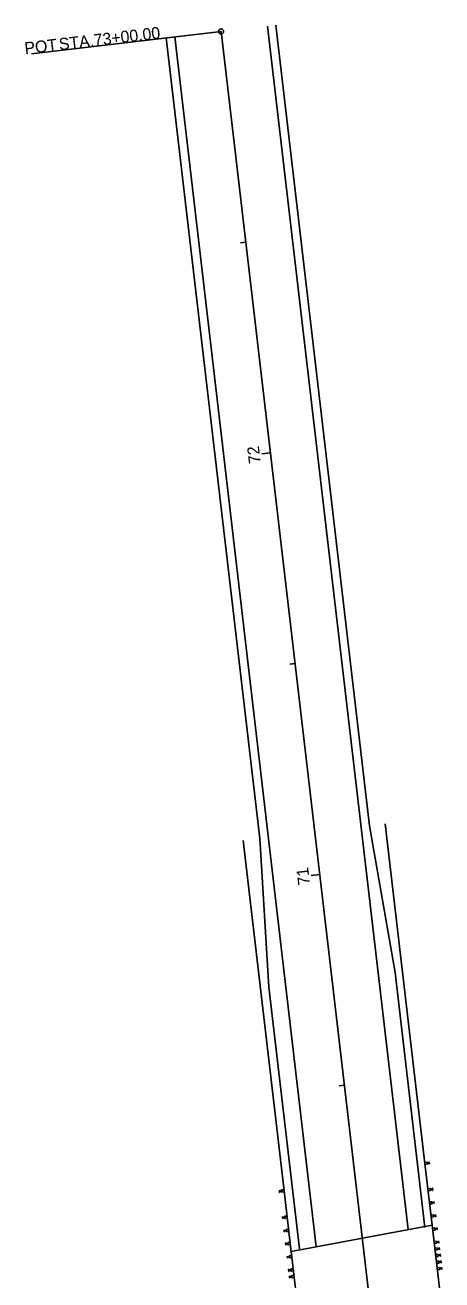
# Model space of a CAD drawing. Extents: x 27625 to 127752, y 6088 to 302357.
# Drawn here: x 127645.5 to 127743.8, y 302061.4 to 302357.1 of the extents above; entities that cross this region are included whole.
import ezdxf

# ---------------------------------------------------------------- set-up
doc = ezdxf.new("R2010")
doc.units = 0
for name, color, linetype in [('DR_X_Cells', 7, 'Continuous'), ('RW_X_CL_100_Bearings', 7, 'Continuous'), ('RW_X_CL_100_Cardinal_Points', 7, 'Continuous'), ('RW_X_CL_100_Curve_Data', 7, 'Continuous'), ('RW_X_CL_100_Distances', 7, 'Continuous'), ('RW_X_CL_100_Stations', 7, 'Continuous'), ('SC_Scratch13', 7, 'Continuous'), ('SC_Scratch2', 7, 'Continuous'), ('SV_P_Control_Cells_Set', 7, 'Continuous'), ('SV_X_Mon_Cells_Found', 7, 'Continuous'), ('SV_X_Random_Point', 7, 'Continuous'), ('UT_X_Telecom_Cells', 7, 'Continuous')]:
    doc.layers.add(name, color=color, linetype=linetype)

msp = doc.modelspace()

# ---------------------------------------------------------------- linework, layer by layer
at = {"layer": 'DR_X_Cells'}
for p, q in [((127697.52, 302305.96), (127696.33, 302305.82)), ((127703.33, 302256.3), (127701.34, 302256.07)), ((127709.14, 302206.64), (127707.94, 302206.5)), ((127714.94, 302156.98), (127712.96, 302156.75)), ((127720.75, 302107.32), (127719.56, 302107.18))]:
    msp.add_line(p, q, dxfattribs=at)
at = {"layer": 'RW_X_CL_100_Bearings'}
for p, q in [((127708.23, 302068.08), (127741.47, 302074.34)), ((127743.22, 302059.45), (127741.47, 302074.34)), ((127709.97, 302053.18), (127708.23, 302068.08))]:
    msp.add_line(p, q, dxfattribs=at)
at = {"layer": 'RW_X_CL_100_Cardinal_Points'}
for p, q in [((127741.47, 302074.34), (127739.78, 302088.84)), ((127739.78, 302088.84), (127739.78, 302088.84)), ((127708.25, 302067.92), (127706.55, 302082.42)), ((127706.55, 302082.42), (127706.55, 302082.42))]:
    msp.add_line(p, q, dxfattribs=at)
at = {"layer": 'RW_X_CL_100_Curve_Data'}
for p, q in [((127739.75, 302089.09), (127740.28, 302089.16)), ((127740.34, 302088.65), (127739.81, 302088.59)), ((127740.34, 302088.65), (127740.28, 302089.16)), ((127740.31, 302089.16), (127740.28, 302089.16)), ((127740.34, 302088.95), (127740.31, 302089.16)), ((127740.37, 302088.65), (127740.34, 302088.65)), ((127740.37, 302088.65), (127740.35, 302088.86)), ((127740.76, 302088.97), (127740.37, 302088.93)), ((127740.77, 302088.94), (127740.38, 302088.9)), ((127740.8, 302089.22), (127740.77, 302089.21)), ((127740.79, 302089.01), (127740.77, 302089.21)), ((127740.86, 302088.71), (127740.8, 302089.22)), ((127740.83, 302088.71), (127740.8, 302088.91)), ((127740.86, 302088.71), (127740.83, 302088.71)), ((127705.52, 302082.04), (127705.47, 302082.55)), ((127705.47, 302082.55), (127705.5, 302082.55)), ((127705.53, 302082.34), (127705.5, 302082.55)), ((127705.52, 302082.04), (127705.56, 302082.04)), ((127705.56, 302082.04), (127705.54, 302082.25)), ((127705.56, 302082.32), (127705.95, 302082.36)), ((127705.56, 302082.29), (127705.96, 302082.33)), ((127705.96, 302082.6), (127705.99, 302082.61)), ((127705.98, 302082.4), (127705.96, 302082.6)), ((127706.52, 302082.67), (127705.99, 302082.61)), ((127706.05, 302082.1), (127705.99, 302082.61)), ((127706.02, 302082.1), (127705.99, 302082.3)), ((127706.02, 302082.1), (127706.05, 302082.1)), ((127706.05, 302082.1), (127706.58, 302082.16)), ((127740.47, 302082.89), (127741, 302082.95)), ((127741.06, 302082.44), (127740.53, 302082.38)), ((127741.06, 302082.44), (127741, 302082.95)), ((127741.04, 302082.95), (127741, 302082.95)), ((127741.06, 302082.75), (127741.04, 302082.95)), ((127741.1, 302082.45), (127741.06, 302082.44)), ((127741.1, 302082.45), (127741.07, 302082.65)), ((127741.49, 302082.76), (127741.1, 302082.72)), ((127741.49, 302082.73), (127741.1, 302082.69)), ((127741.53, 302083.01), (127741.49, 302083.01)), ((127741.52, 302082.8), (127741.49, 302083.01)), ((127741.59, 302082.5), (127741.53, 302083.01)), ((127741.55, 302082.5), (127741.53, 302082.71)), ((127741.59, 302082.5), (127741.55, 302082.5)), ((127740.84, 302079.78), (127741.37, 302079.84)), ((127741.42, 302079.34), (127740.9, 302079.28)), ((127741.4, 302079.85), (127741.37, 302079.84)), ((127741.42, 302079.34), (127741.37, 302079.84)), ((127741.43, 302079.64), (127741.4, 302079.85)), ((127741.46, 302079.34), (127741.42, 302079.34)), ((127741.46, 302079.34), (127741.44, 302079.55)), ((127741.85, 302079.66), (127741.46, 302079.61)), ((127741.86, 302079.63), (127741.46, 302079.58)), ((127741.89, 302079.91), (127741.86, 302079.9)), ((127741.88, 302079.7), (127741.86, 302079.9)), ((127741.95, 302079.4), (127741.89, 302079.91)), ((127741.92, 302079.4), (127741.89, 302079.6)), ((127741.95, 302079.4), (127741.92, 302079.4)), ((127706.25, 302075.83), (127706.19, 302076.34)), ((127706.19, 302076.34), (127706.23, 302076.34)), ((127706.25, 302076.14), (127706.23, 302076.34)), ((127706.25, 302075.83), (127706.29, 302075.84)), ((127706.29, 302075.84), (127706.26, 302076.04)), ((127706.29, 302076.11), (127706.68, 302076.16)), ((127706.29, 302076.08), (127706.68, 302076.12)), ((127706.68, 302076.4), (127706.72, 302076.4)), ((127706.71, 302076.19), (127706.68, 302076.4)), ((127707.25, 302076.46), (127706.72, 302076.4)), ((127706.78, 302075.89), (127706.72, 302076.4)), ((127706.74, 302075.89), (127706.72, 302076.1)), ((127706.74, 302075.89), (127706.78, 302075.89)), ((127706.78, 302075.89), (127707.31, 302075.96)), ((127741.2, 302076.68), (127741.73, 302076.74)), ((127741.79, 302076.23), (127741.26, 302076.17)), ((127741.76, 302076.75), (127741.73, 302076.74)), ((127741.79, 302076.23), (127741.73, 302076.74)), ((127741.79, 302076.54), (127741.76, 302076.75)), ((127741.82, 302076.24), (127741.79, 302076.23)), ((127741.82, 302076.24), (127741.8, 302076.45)), ((127742.22, 302076.56), (127741.82, 302076.51)), ((127742.22, 302076.53), (127741.83, 302076.48)), ((127742.26, 302076.8), (127742.22, 302076.8)), ((127742.24, 302076.59), (127742.22, 302076.8)), ((127742.32, 302076.3), (127742.26, 302076.8)), ((127742.28, 302076.29), (127742.26, 302076.5)), ((127742.32, 302076.3), (127742.28, 302076.29)), ((127706.61, 302072.73), (127706.55, 302073.24)), ((127706.55, 302073.24), (127706.59, 302073.24)), ((127706.61, 302073.03), (127706.59, 302073.24)), ((127706.61, 302072.73), (127706.65, 302072.73)), ((127706.65, 302072.73), (127706.63, 302072.94)), ((127706.65, 302073.01), (127707.04, 302073.05)), ((127706.65, 302072.97), (127707.05, 302073.02)), ((127707.05, 302073.29), (127707.08, 302073.3)), ((127707.07, 302073.09), (127707.05, 302073.29)), ((127707.61, 302073.36), (127707.08, 302073.3)), ((127707.14, 302072.79), (127707.08, 302073.3)), ((127707.1, 302072.79), (127707.08, 302072.99)), ((127707.1, 302072.79), (127707.14, 302072.79)), ((127707.14, 302072.79), (127707.67, 302072.85)), ((127741.56, 302073.58), (127742.09, 302073.64)), ((127742.15, 302073.13), (127741.62, 302073.07)), ((127742.15, 302073.13), (127742.09, 302073.64)), ((127742.13, 302073.64), (127742.09, 302073.64)), ((127742.15, 302073.43), (127742.13, 302073.64)), ((127742.19, 302073.13), (127742.15, 302073.13)), ((127742.19, 302073.13), (127742.16, 302073.34)), ((127742.58, 302073.45), (127742.19, 302073.41)), ((127742.58, 302073.42), (127742.19, 302073.38)), ((127742.62, 302073.7), (127742.58, 302073.69)), ((127742.61, 302073.49), (127742.58, 302073.69)), ((127742.68, 302073.19), (127742.62, 302073.7)), ((127742.64, 302073.19), (127742.62, 302073.39)), ((127742.68, 302073.19), (127742.64, 302073.19)), ((127706.92, 302070.13), (127706.95, 302070.14)), ((127706.98, 302069.63), (127706.92, 302070.13)), ((127706.98, 302069.93), (127706.95, 302070.14)), ((127706.98, 302069.63), (127707.01, 302069.63)), ((127707.01, 302069.63), (127706.99, 302069.84)), ((127707.01, 302069.9), (127707.41, 302069.95)), ((127707.02, 302069.87), (127707.41, 302069.92)), ((127707.41, 302070.19), (127707.44, 302070.19)), ((127707.43, 302069.98), (127707.41, 302070.19)), ((127707.97, 302070.26), (127707.44, 302070.19)), ((127707.5, 302069.69), (127707.44, 302070.19)), ((127707.47, 302069.68), (127707.44, 302069.89)), ((127707.47, 302069.68), (127707.5, 302069.69)), ((127707.5, 302069.69), (127708.03, 302069.75)), ((127741.93, 302070.47), (127742.45, 302070.53)), ((127742.51, 302070.03), (127741.99, 302069.96)), ((127742.11, 302068.92), (127742.64, 302068.98)), ((127742.49, 302070.54), (127742.45, 302070.53)), ((127742.51, 302070.03), (127742.45, 302070.53)), ((127742.52, 302070.33), (127742.49, 302070.54)), ((127742.55, 302070.03), (127742.51, 302070.03)), ((127742.55, 302070.03), (127742.53, 302070.24)), ((127742.94, 302070.35), (127742.55, 302070.3)), ((127742.95, 302070.32), (127742.55, 302070.27)), ((127742.67, 302068.99), (127742.64, 302068.98)), ((127742.7, 302068.47), (127742.64, 302068.98)), ((127742.7, 302068.78), (127742.67, 302068.99)), ((127743.12, 302068.8), (127742.73, 302068.75)), ((127743.13, 302068.77), (127742.73, 302068.72)), ((127742.98, 302070.59), (127742.95, 302070.59)), ((127742.97, 302070.38), (127742.95, 302070.59)), ((127743.04, 302070.09), (127742.98, 302070.59)), ((127743.01, 302070.08), (127742.98, 302070.29)), ((127743.04, 302070.09), (127743.01, 302070.08)), ((127743.16, 302069.04), (127743.13, 302069.04)), ((127743.15, 302068.83), (127743.13, 302069.04)), ((127743.22, 302068.54), (127743.16, 302069.04)), ((127707.34, 302066.52), (127707.28, 302067.03)), ((127707.28, 302067.03), (127707.32, 302067.03)), ((127707.34, 302066.83), (127707.32, 302067.03)), ((127707.34, 302066.52), (127707.38, 302066.53)), ((127707.38, 302066.53), (127707.35, 302066.73)), ((127707.38, 302066.8), (127707.77, 302066.84)), ((127707.38, 302066.77), (127707.77, 302066.81)), ((127707.77, 302067.09), (127707.81, 302067.09)), ((127707.8, 302066.88), (127707.77, 302067.09)), ((127708.34, 302067.15), (127707.81, 302067.09)), ((127707.87, 302066.58), (127707.81, 302067.09)), ((127707.83, 302066.58), (127707.81, 302066.79)), ((127707.83, 302066.58), (127707.87, 302066.58)), ((127707.87, 302066.58), (127708.39, 302066.64)), ((127742.7, 302068.47), (127742.17, 302068.41)), ((127742.29, 302067.37), (127742.82, 302067.43)), ((127742.88, 302066.92), (127742.35, 302066.86)), ((127742.47, 302065.82), (127743, 302065.88)), ((127742.73, 302068.48), (127742.7, 302068.47)), ((127742.73, 302068.48), (127742.71, 302068.69)), ((127742.88, 302066.92), (127742.82, 302067.43)), ((127742.85, 302067.43), (127742.82, 302067.43)), ((127742.88, 302067.23), (127742.85, 302067.43)), ((127742.91, 302066.93), (127742.88, 302066.92)), ((127742.91, 302066.93), (127742.89, 302067.13)), ((127743.31, 302067.25), (127742.91, 302067.2)), ((127743.31, 302067.21), (127742.92, 302067.17)), ((127743.06, 302065.37), (127743, 302065.88)), ((127743.04, 302065.88), (127743, 302065.88)), ((127743.06, 302065.67), (127743.04, 302065.88)), ((127743.19, 302068.53), (127743.16, 302068.74)), ((127743.22, 302068.54), (127743.19, 302068.53)), ((127743.35, 302067.49), (127743.31, 302067.49)), ((127743.33, 302067.28), (127743.31, 302067.49)), ((127743.37, 302066.98), (127743.34, 302067.19)), ((127743.4, 302066.98), (127743.35, 302067.49)), ((127743.4, 302066.98), (127743.37, 302066.98)), ((127743.53, 302065.94), (127743.49, 302065.94)), ((127743.51, 302065.73), (127743.49, 302065.94)), ((127743.59, 302065.43), (127743.53, 302065.94)), ((127707.64, 302063.92), (127707.68, 302063.93)), ((127707.7, 302063.42), (127707.64, 302063.92)), ((127707.7, 302063.72), (127707.68, 302063.93)), ((127707.7, 302063.42), (127707.74, 302063.42)), ((127707.74, 302063.42), (127707.71, 302063.63)), ((127707.74, 302063.69), (127708.13, 302063.74)), ((127707.74, 302063.66), (127708.14, 302063.71)), ((127708.13, 302063.98), (127708.17, 302063.99)), ((127708.16, 302063.77), (127708.13, 302063.98)), ((127708.7, 302064.05), (127708.17, 302063.99)), ((127708.23, 302063.48), (127708.17, 302063.99)), ((127708.19, 302063.47), (127708.17, 302063.68)), ((127708.19, 302063.47), (127708.23, 302063.48)), ((127708.23, 302063.48), (127708.76, 302063.54)), ((127743.06, 302065.37), (127742.53, 302065.31)), ((127742.65, 302064.26), (127743.18, 302064.33)), ((127743.24, 302063.82), (127742.71, 302063.76)), ((127743.09, 302065.37), (127743.06, 302065.37)), ((127743.09, 302065.37), (127743.07, 302065.58)), ((127743.49, 302065.69), (127743.09, 302065.65)), ((127743.49, 302065.66), (127743.1, 302065.62)), ((127743.24, 302063.82), (127743.18, 302064.33)), ((127743.22, 302064.33), (127743.18, 302064.33)), ((127743.24, 302064.12), (127743.22, 302064.33)), ((127743.28, 302063.82), (127743.24, 302063.82)), ((127743.28, 302063.82), (127743.25, 302064.03)), ((127743.67, 302064.14), (127743.28, 302064.1)), ((127743.67, 302064.11), (127743.28, 302064.06)), ((127743.55, 302065.43), (127743.53, 302065.64)), ((127743.59, 302065.43), (127743.55, 302065.43)), ((127743.71, 302064.39), (127743.67, 302064.38)), ((127743.7, 302064.18), (127743.67, 302064.38)), ((127743.77, 302063.88), (127743.71, 302064.39)), ((127743.73, 302063.88), (127743.71, 302064.08)), ((127743.77, 302063.88), (127743.73, 302063.88)), ((127707.82, 302062.37), (127707.86, 302062.38)), ((127707.88, 302061.87), (127707.82, 302062.37)), ((127707.89, 302062.17), (127707.86, 302062.38)), ((127707.88, 302061.87), (127707.92, 302061.87)), ((127707.92, 302061.87), (127707.9, 302062.08)), ((127707.92, 302062.14), (127708.31, 302062.19)), ((127707.92, 302062.11), (127708.32, 302062.16)), ((127708.32, 302062.43), (127708.35, 302062.43)), ((127708.34, 302062.22), (127708.32, 302062.43)), ((127708.88, 302062.5), (127708.35, 302062.43)), ((127708.41, 302061.93), (127708.35, 302062.43)), ((127708.38, 302061.92), (127708.35, 302062.13)), ((127708.38, 302061.92), (127708.41, 302061.93)), ((127708.41, 302061.93), (127708.94, 302061.99))]:
    msp.add_line(p, q, dxfattribs=at)
for centre, start, end in [((127740.37, 302088.96), 186.6714, 276.6714), ((127740.38, 302088.86), 96.6714, 186.6714), ((127740.76, 302089), 276.6714, 6.6714), ((127740.77, 302088.91), 6.6714, 96.6714), ((127705.56, 302082.35), 186.6714, 276.6714), ((127705.57, 302082.26), 96.6714, 186.6714), ((127705.95, 302082.39), 276.6714, 6.6714), ((127705.96, 302082.3), 6.6714, 96.6714), ((127741.09, 302082.75), 186.6714, 276.6714), ((127741.1, 302082.66), 96.6714, 186.6714), ((127741.49, 302082.8), 276.6714, 6.6714), ((127741.5, 302082.7), 6.6714, 96.6714), ((127741.46, 302079.65), 186.6714, 276.6714), ((127741.47, 302079.55), 96.6714, 186.6714), ((127741.85, 302079.69), 276.6714, 6.6714), ((127741.86, 302079.6), 6.6714, 96.6714), ((127706.28, 302076.14), 186.6714, 276.6714), ((127706.29, 302076.05), 96.6714, 186.6714), ((127706.68, 302076.19), 276.6714, 6.6714), ((127706.69, 302076.09), 6.6714, 96.6714), ((127741.82, 302076.54), 186.6714, 276.6714), ((127741.83, 302076.45), 96.6714, 186.6714), ((127742.21, 302076.59), 276.6714, 6.6714), ((127742.22, 302076.49), 6.6714, 96.6714), ((127706.65, 302073.04), 186.6714, 276.6714), ((127706.66, 302072.94), 96.6714, 186.6714), ((127707.04, 302073.08), 276.6714, 6.6714), ((127707.05, 302072.99), 6.6714, 96.6714), ((127742.18, 302073.44), 186.6714, 276.6714), ((127742.19, 302073.35), 96.6714, 186.6714), ((127742.58, 302073.48), 276.6714, 6.6714), ((127742.59, 302073.39), 6.6714, 96.6714), ((127707.01, 302069.93), 186.6714, 276.6714), ((127707.02, 302069.84), 96.6714, 186.6714), ((127707.4, 302069.98), 276.6714, 6.6714), ((127707.41, 302069.89), 6.6714, 96.6714), ((127742.55, 302070.33), 186.6714, 276.6714), ((127742.56, 302070.24), 96.6714, 186.6714), ((127742.73, 302068.78), 186.6714, 276.6714), ((127742.94, 302070.38), 276.6714, 6.6714), ((127742.95, 302070.29), 6.6714, 96.6714), ((127743.12, 302068.83), 276.6714, 6.6714), ((127743.13, 302068.74), 6.6714, 96.6714), ((127707.37, 302066.83), 186.6714, 276.6714), ((127707.38, 302066.74), 96.6714, 186.6714), ((127707.76, 302066.88), 276.6714, 6.6714), ((127707.78, 302066.78), 6.6714, 96.6714), ((127742.74, 302068.69), 96.6714, 186.6714), ((127742.91, 302067.23), 186.6714, 276.6714), ((127742.92, 302067.14), 96.6714, 186.6714), ((127743.3, 302067.28), 276.6714, 6.6714), ((127743.31, 302067.18), 6.6714, 96.6714), ((127707.73, 302063.73), 186.6714, 276.6714), ((127707.75, 302063.63), 96.6714, 186.6714), ((127708.13, 302063.77), 276.6714, 6.6714), ((127708.14, 302063.68), 6.6714, 96.6714), ((127743.09, 302065.68), 186.6714, 276.6714), ((127743.1, 302065.59), 96.6714, 186.6714), ((127743.27, 302064.13), 186.6714, 276.6714), ((127743.28, 302064.03), 96.6714, 186.6714), ((127743.48, 302065.72), 276.6714, 6.6714), ((127743.49, 302065.63), 6.6714, 96.6714), ((127743.67, 302064.17), 276.6714, 6.6714), ((127743.68, 302064.08), 6.6714, 96.6714), ((127707.92, 302062.17), 186.6714, 276.6714), ((127707.93, 302062.08), 96.6714, 186.6714), ((127708.31, 302062.22), 276.6714, 6.6714), ((127708.32, 302062.13), 6.6714, 96.6714)]:
    msp.add_arc(centre, 0.0312, start, end, dxfattribs=at)
at = {"layer": 'RW_X_CL_100_Distances'}
msp.add_line((127739.78, 302088.84), (127730.42, 302168.86), dxfattribs=at)
at = {"layer": 'RW_X_CL_100_Stations'}
for p, q in [((127739.81, 302088.59), (127739.75, 302089.09)), ((127706.58, 302082.16), (127706.52, 302082.67)), ((127740.53, 302082.38), (127740.47, 302082.89)), ((127740.9, 302079.28), (127740.84, 302079.78)), ((127707.31, 302075.96), (127707.25, 302076.46)), ((127741.26, 302076.17), (127741.2, 302076.68)), ((127707.67, 302072.85), (127707.61, 302073.36)), ((127741.62, 302073.07), (127741.56, 302073.58)), ((127708.03, 302069.75), (127707.97, 302070.26)), ((127741.99, 302069.96), (127741.93, 302070.47)), ((127742.17, 302068.41), (127742.11, 302068.92)), ((127708.39, 302066.64), (127708.34, 302067.15)), ((127742.35, 302066.86), (127742.29, 302067.37)), ((127742.53, 302065.31), (127742.47, 302065.82)), ((127708.76, 302063.54), (127708.7, 302064.05)), ((127742.71, 302063.76), (127742.65, 302064.26)), ((127708.94, 302061.99), (127708.88, 302062.5))]:
    msp.add_line(p, q, dxfattribs=at)
at = {"layer": 'SC_Scratch13'}
msp.add_line((127732.33, 302008.36), (127691.71, 302355.62), dxfattribs=at)
at = {"layer": 'SC_Scratch2'}
msp.add_line((127691.71, 302355.62), (127670.28, 302353.12), dxfattribs=at)
at = {"layer": 'SV_P_Control_Cells_Set'}
msp.add_line((127706.55, 302082.42), (127696.9, 302164.93), dxfattribs=at)
at = {"layer": 'SV_X_Mon_Cells_Found'}
msp.add_line((127691.71, 302355.62), (127647.01, 302350.39), dxfattribs=at)
msp.add_circle((127691.71, 302355.62), 0.6, dxfattribs=at)
at = {"layer": 'SV_X_Random_Point'}
for p, q in [((127704.62, 302357.13), (127726.69, 302168.42)), ((127678.8, 302354.11), (127700.87, 302165.4)), ((127726.69, 302168.42), (127732.75, 302133.89)), ((127700.87, 302165.4), (127702.95, 302130.4)), ((127732.75, 302133.89), (127739.78, 302073.74)), ((127702.95, 302130.4), (127710.16, 302068.73))]:
    msp.add_line(p, q, dxfattribs=at)
at = {"layer": 'UT_X_Telecom_Cells'}
for p, q in [((127702.64, 302356.9), (127735.81, 302073.28)), ((127680.78, 302354.34), (127714.14, 302069.19))]:
    msp.add_line(p, q, dxfattribs=at)

# ---------------------------------------------------------------- texts
at = {"layer": 'DR_X_Cells'}
for s, p in [('72', (127701.09, 302253.93)), ('71', (127712.71, 302154.6))]:
    msp.add_text(s, height=2.8, rotation=96.6714, dxfattribs=at).set_placement(p)
at = {"layer": 'SV_X_Mon_Cells_Found'}
for s, p in [('73+00.00', (127661.88, 302352.17)), ('POT', (127645.54, 302350.26)), (' STA. ', (127652.62, 302351.09))]:
    msp.add_text(s, height=2.8, rotation=6.6714, dxfattribs=at).set_placement(p)

doc.saveas('drawing.dxf')
